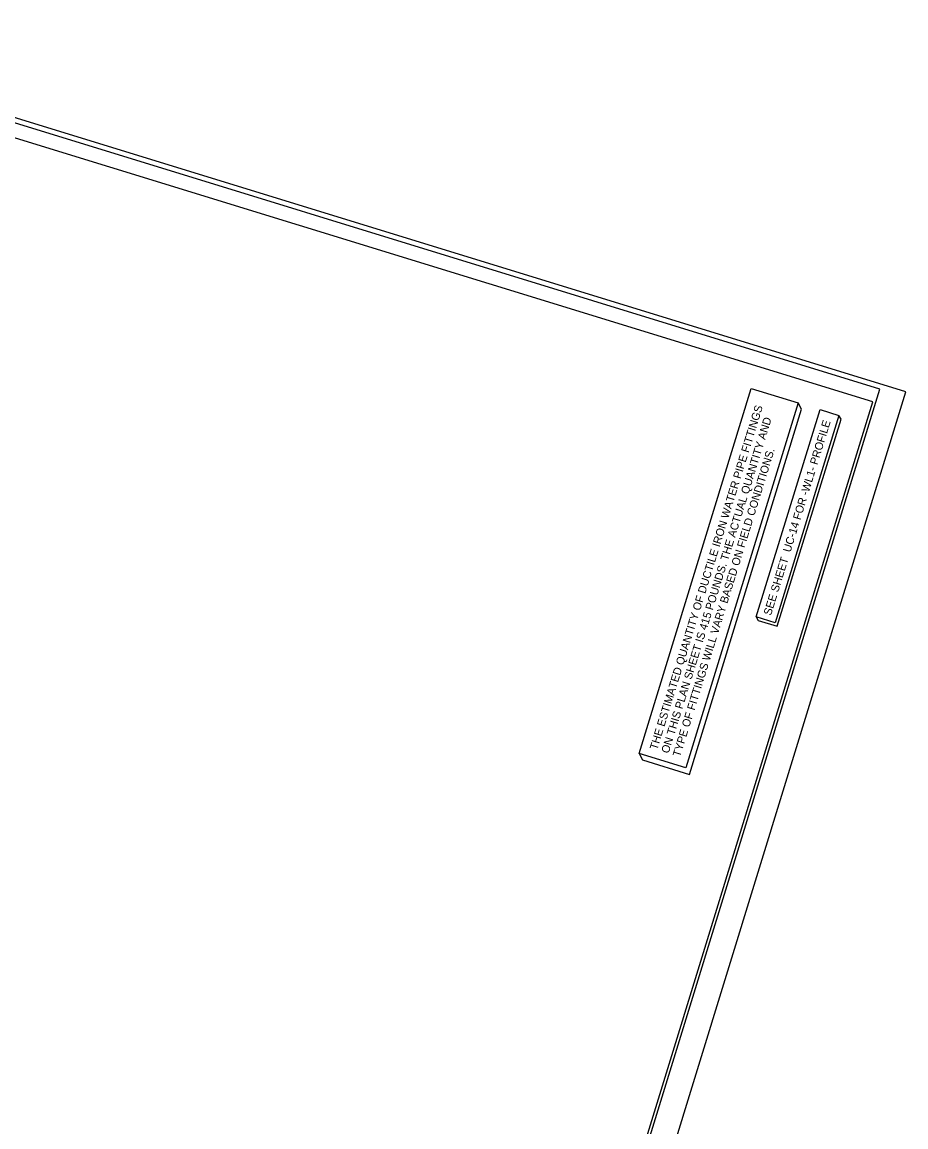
# Model space of a CAD drawing. Extents: x 1439200 to 1642353, y 394562 to 606444.
# Drawn here: x 1642044.2 to 1642353.5, y 394948.2 to 395334.8 of the extents above; entities that cross this region are included whole.
import ezdxf

# ---------------------------------------------------------------- set-up
doc = ezdxf.new("R2010")
doc.units = 0
for name, color, linetype in [('Sheet Data Text CELL', 7, 'Continuous'), ('Sheet Plot Border Inside CELL', 7, 'Continuous'), ('Sheet Plot Border Outside CELL', 7, 'Continuous'), ('UC Plan Sheet 34 CELL', 7, 'Continuous')]:
    doc.layers.add(name, color=color, linetype=linetype)

msp = doc.modelspace()

# ---------------------------------------------------------------- linework, layer by layer
at = {"layer": 'Sheet Data Text CELL'}
for p, q in [((1642277.7, 395071.59), (1642316.99, 395199.34)), ((1642316.99, 395199.34), (1642315.8, 395201.59)), ((1642330.8, 395195.92), (1642330.02, 395197.22)), ((1642301.14, 395126.7), (1642301.8, 395125.46)), ((1642260.1, 395078.89), (1642261.29, 395076.64)), ((1642261.29, 395076.64), (1642277.7, 395071.59))]:
    msp.add_line(p, q, dxfattribs=at)
for points in [[(1642260.1, 395078.89), (1642299.39, 395206.64), (1642315.8, 395201.59), (1642276.51, 395073.84)], [(1642301.14, 395126.7), (1642323.45, 395199.24), (1642330.02, 395197.22), (1642307.71, 395124.68)]]:
    msp.add_lwpolyline(points, close=True, dxfattribs=at)
for points in [[(1642315.8, 395201.59), (1642276.51, 395073.84), (1642260.1, 395078.89)], [(1642330.02, 395197.22), (1642307.71, 395124.68), (1642301.14, 395126.7)], [(1642301.8, 395125.46), (1642308.49, 395123.4), (1642330.8, 395195.92)]]:
    msp.add_lwpolyline(points, dxfattribs=at)
at = {"layer": 'Sheet Plot Border Inside CELL'}
msp.add_lwpolyline([(1641940.98, 395330.47), (1641745.02, 394693.33), (1642148.41, 394569.26), (1642344.38, 395206.4)], close=True, dxfattribs=at)
at = {"layer": 'Sheet Plot Border Outside CELL'}
msp.add_lwpolyline([(1641932.93, 395334.83), (1641734.91, 394691), (1642155.47, 394561.65), (1642353.49, 395205.48)], close=True, dxfattribs=at)
at = {"layer": 'UC Plan Sheet 34 CELL'}
msp.add_lwpolyline([(1641940.49, 395325.39), (1641764.1, 394751.91), (1642165.54, 394628.44), (1642341.93, 395201.92)], close=True, dxfattribs=at)

# ---------------------------------------------------------------- texts
at = {"layer": 'Sheet Data Text CELL'}
for s, p in [('THE ESTIMATED QUANTITY OF DUCTILE IRON WATER PIPE FITTINGS ', (1642266.45, 395079.97)), ('ON THIS PLAN SHEET IS 415 POUNDS. THE ACTUAL QUANTITY AND ', (1642270.46, 395078.74)), ('SEE SHEET  UC-14 FOR -WL1- PROFILE', (1642306.27, 395127.02)), ('TYPE OF FITTINGS WILL VARY BASED ON FIELD CONDITIONS.', (1642274.47, 395077.51))]:
    msp.add_text(s, height=2.8, rotation=72.9038, dxfattribs=at).set_placement(p)

doc.saveas('drawing.dxf')
